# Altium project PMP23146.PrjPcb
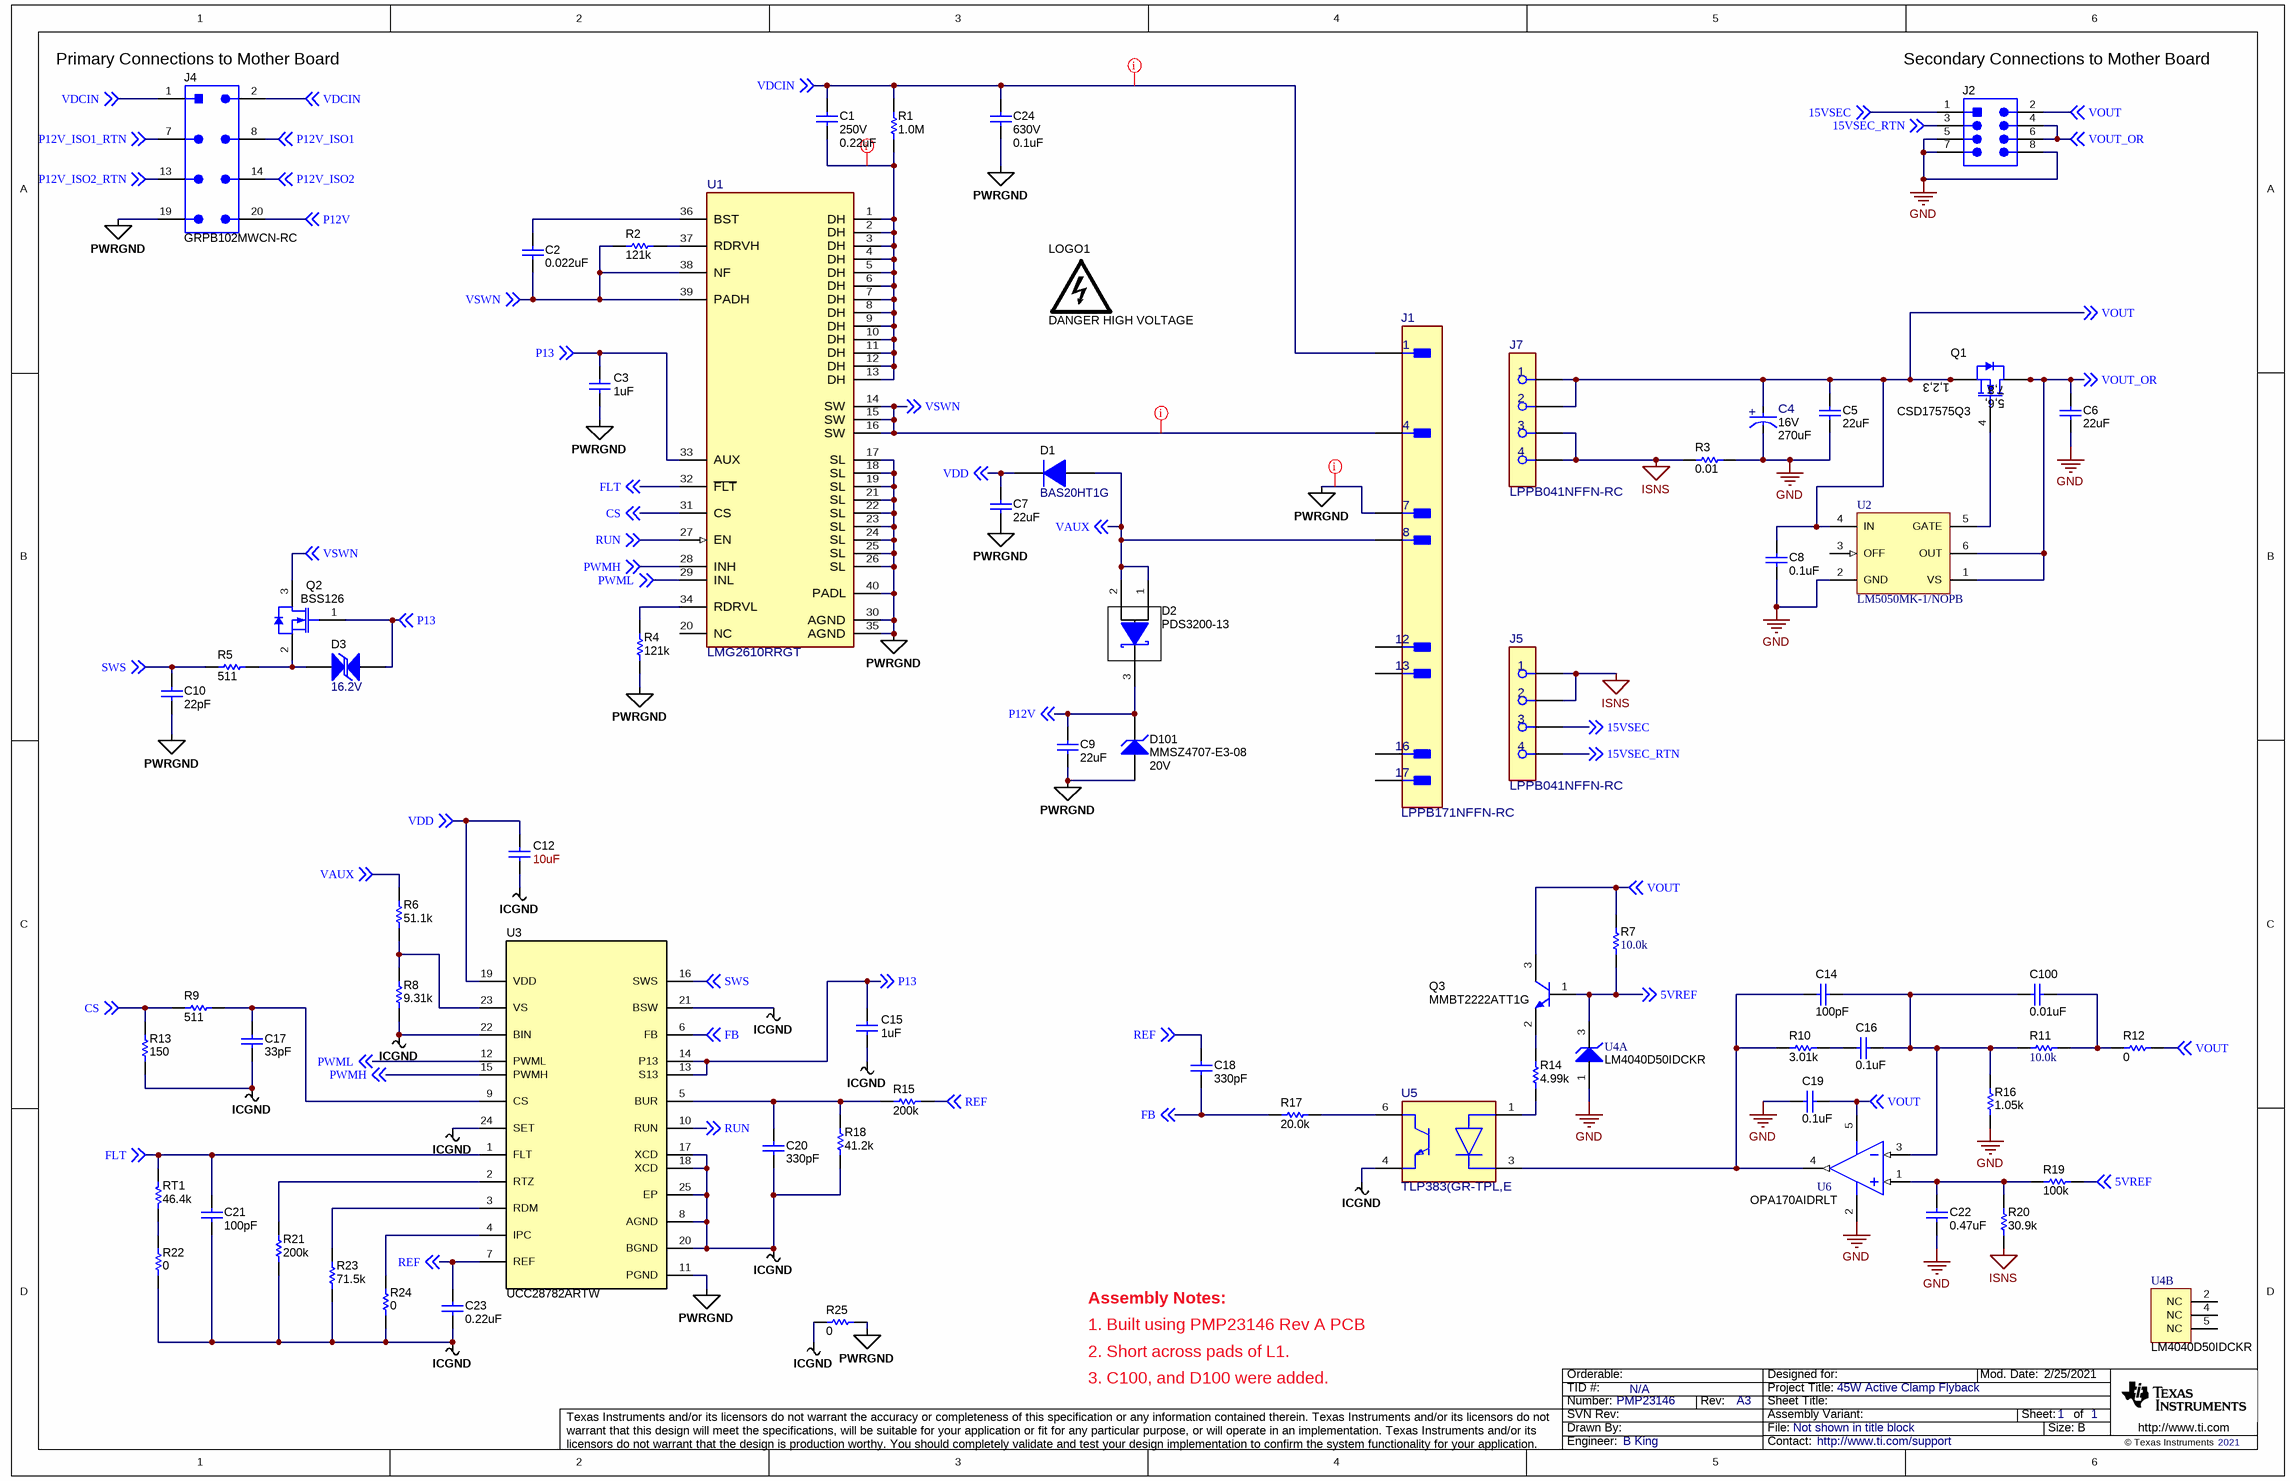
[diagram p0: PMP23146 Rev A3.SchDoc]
TID: N/A; TechSupport: http://www.ti.com/support; SCH_Rev: A3; PRJ_Title: 45W Active Clamp Flyback; PRJ_Number: PMP23146; PRJ_Engineer: B King; PCB_Rev: A; PCB_Layout: B King; CopyrightYear: 2021
1 sheet, 68 parts. Net scope: global (net labels, ports and power ports of the same name join across sheets).
Board file: PMP23146 Rev A.PcbDoc

## Sheet PMP23146 Rev A3.SchDoc
size 431 x 279 mm; Date: Not shown in title block; ApprovedBy: Not shown in title block; CheckedBy: Not shown in title block; Author: Not shown in title block; CompanyName: Not shown in title block; Engineer: Not shown in title block; Organization: Not shown in title block; Address1: Not shown in title block; Address2: Not shown in title block; Address3: Not shown in title block; Address4: Not shown in title block; DocumentNumber: 1; Revision: Use project parameter SCH_Rev; SheetNumber: 1; SheetTotal: 1; PageSetup: Record=PageOptions¦CenterHorizontal=True¦CenterVertical=True¦PrintScale=1.00¦XCorrection=1.00¦YCorrection=1.00¦PrintKind=0¦BorderSize=5000000¦LeftOffset=0¦BottomOffset=0¦Orientation=2¦PaperLength=1000¦PaperWidth=1000¦Scale=100¦PaperSource=15¦PrintQuality=600¦MediaType=1¦DitherType=10¦PaperKind=Letter¦PrintScaleMode=1

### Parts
C1  VDC_V: 250V  ValueDisplayed: 0.22uF  [1206_190L]  (hidden comment: C3216X7T2E224K160AA)
C2  ValueDisplayed: 0.022uF  [0402S]  (hidden comment: GRM155R71H223KA12D)
C3  ValueDisplayed: 1uF  [0603S]  (hidden comment: C1608X7R1E105K080AB)
C4  VDC_V: 16V  ValueDisplayed: 270uF  [FP-APSG160ELL271MF08J_RADIAL-MFG]  (hidden comment: APSG160ELL271MF08J)
C5  ValueDisplayed: 22uF  [1206_180L]  (hidden comment: C3216X5R1V226M160AC)
C6  ValueDisplayed: 22uF  [1206_180L]  (hidden comment: C3216X5R1V226M160AC)
C7  ValueDisplayed: 22uF  [1206_180L]  (hidden comment: C3216X5R1V226M160AC)
C8  ValueDisplayed: 0.1uF  [0402S]  (hidden comment: GRM155R71E104KE14D)
C9  ValueDisplayed: 22uF  [1206_180L]  (hidden comment: C3216X5R1V226M160AC)
C10  ValueDisplayed: 22pF  [0402S]  (hidden comment: GRM1555C1H220JA01D)
C12  ValueDisplayed: 10uF  [0603S]  (hidden comment: GRM188R6YA106MA73D)
C14  ValueDisplayed: 100pF  [0402S]  (hidden comment: GRM1555C1H101JA01D)
C15  ValueDisplayed: 1uF  [0603S]  (hidden comment: C1608X7R1E105K080AB)
C16  ValueDisplayed: 0.1uF  [0402S]  (hidden comment: GRM155R71E104KE14D)
C17  ValueDisplayed: 33pF  [0402S]  (hidden comment: GRM1555C1H330JA01D)
C18  ValueDisplayed: 330pF  [0402S]  (hidden comment: GRM155R71H331KA01D)
C19  ValueDisplayed: 0.1uF  [0402S]  (hidden comment: GRM155R71E104KE14D)
C20  ValueDisplayed: 330pF  [0402S]  (hidden comment: GRM155R71H331KA01D)
C21  ValueDisplayed: 100pF  [0402S]  (hidden comment: GRM1555C1H101JA01D)
C22  ValueDisplayed: 0.47uF  [0402]  (hidden comment: C1005X5R1A474K050BB)
C23  ValueDisplayed: 0.22uF  [0402S]  (hidden comment: GRM155R71C224KA12D)
C24  VDC_V: 630V  ValueDisplayed: 0.1uF  [1808_215_L]  (hidden comment: C1808W104KBRACTU)
C100  ValueDisplayed: 0.01uF  [0402S]  (hidden comment: GCM155R71E103KA37D)
D1  BAS20HT1G  [SOD-323]
D2  PDS3200-13  [POWERDI5]
D3  value 16.2V  [SOD-323-Bi]  (hidden comment: DF2B18FU)
D101  MMSZ4707-E3-08  value 20V  [SOD-123]
J1  LPPB171NFFN-RC  [FP-GRPB171VWVN-RC_HDR17-MFG]
J2  GRPB042MWCN-RC  [Sullins_GRPB042MWCN]  (value not drawn)
J4  GRPB102MWCN-RC  [Sullins_GRPB102MWCN-modified]
J5  LPPB041NFFN-RC  [FP-LPPB041NFFN-RC_HDR04-MFG]
J7  LPPB041NFFN-RC  [FP-LPPB041NFFN-RC_HDR04-MFG]
LOGO1  DANGER HIGH VOLTAGE  [IEC_HighVoltage_Small]  (no BOM)
Q1  CSD17575Q3  [DQG0008A_NV]
Q2  BSS126  [SOT-23L]
Q3  MMBT2222ATT1G  [SOT-416]
R1  ValueDisplayed: 1.0M  [1206L]  (hidden comment: CRCW12061M00JNEA)
R2  ValueDisplayed: 121k  [0402S]  (hidden comment: CRCW0402121KFKED)
R3  ValueDisplayed: 0.01  [1206L]  (hidden comment: CSR1206FK10L0)
R4  ValueDisplayed: 121k  [0402S]  (hidden comment: CRCW0402121KFKED)
R5  ValueDisplayed: 511  [0402S]  (hidden comment: CRCW0402511RFKED)
R6  ValueDisplayed: 51.1k  [0402S]  (hidden comment: CRCW040251K1FKED)
R7  ValueDisplayed: 10.0k  [0402S]  (hidden comment: CRCW040210K0FKED)
R8  ValueDisplayed: 9.31k  [0402S]  (hidden comment: CRCW04029K31FKED)
R9  ValueDisplayed: 511  [0402S]  (hidden comment: CRCW0402511RFKED)
R10  ValueDisplayed: 3.01k  [0402S]  (hidden comment: CRCW04023K01FKED)
R11  ValueDisplayed: 10.0k  [0402S]  (hidden comment: CRCW040210K0FKED)
R12  ValueDisplayed: 0  [0402S]  (hidden comment: RC0402JR-070RL)
R13  ValueDisplayed: 150  [0402S]  (hidden comment: CRCW0402150RFKED)
R14  ValueDisplayed: 4.99k  [0402S]  (hidden comment: CRCW04024K99FKED)
R15  ValueDisplayed: 200k  [0402S]  (hidden comment: CRCW0402200KFKED)
R16  ValueDisplayed: 1.05k  [0402S]  (hidden comment: CRCW04021K05FKED)
R17  ValueDisplayed: 20.0k  [0402S]  (hidden comment: CRCW040220K0FKED)
R18  ValueDisplayed: 41.2k  [0402S]  (hidden comment: CRCW040241K2FKED)
R19  ValueDisplayed: 100k  [0402S]  (hidden comment: CRCW0402100KFKED)
R20  ValueDisplayed: 30.9k  [0402S]  (hidden comment: CRCW040230K9FKED)
R21  ValueDisplayed: 200k  [0402S]  (hidden comment: CRCW0402200KFKED)
R22  ValueDisplayed: 0  [0402S]  (hidden comment: CRCW04020000Z0ED)
R23  ValueDisplayed: 71.5k  [0402S]  (hidden comment: CRCW040271K5FKED)
R24  ValueDisplayed: 0  [0402S]  (hidden comment: CRCW04020000Z0ED)
R25  ValueDisplayed: 0  [0402S]  (hidden comment: CRCW04020000Z0ED)
RT1  ValueDisplayed: 46.4k  [0603L]  (hidden comment: CRCW060346K4FKEA)
U1  LMG2610RRGT  [RRG0038A-MFG]
U2  LM5050MK-1/NOPB  [DDC0006A_L]
U3  UCC28782ARTW  [RTW0024B]
U4  LM4040D50IDCKR  [DCK0005A_L]  (parts A,B of 2)
U5  TLP383(GR-TPL,E  [FP-TLP383(GR-TPL,E_SO6-4-MFG]
U6  OPA170AIDRLT  [DRL0005A]

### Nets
GND: C4.1(CATHODE) C5.1 C6.2 C8.2 C19.1 C22.1 J2.5 J2.7 J2.8 R3.2 R16.1 U2.2(GND) U4.1(ANODE) U6.2(V-)
ICGND: C12.2 C15.1 C17.2 C20.1 C21.2 C23.2 R8.1 R13.1 R18.1 R21.1 R22.1 R23.1 R24.1 R25.2 U3.8(AGND) U3.17(XCD) U3.18(XCD) U3.20(BGND) U3.21(BSW) U3.22(BIN) U3.24(SET) U3.25(EP) U5.4(Emitter)
ISNS: J5.1 J5.2 J7.3 J7.4 R3.1 R20.1
PWRGND: C3.1 C7.2 C9.2 C10.1 C24.2 D101.2(A) J1.7 J4.19 R4.1 R25.1 U1.17(SL) U1.18(SL) U1.19(SL) U1.21(SL) U1.22(SL) U1.23(SL) U1.24(SL) U1.25(SL) U1.26(SL) U1.30(AGND) U1.35(AGND) U1.40(PADL) U3.11(PGND)
5VREF: Q3.1(B) R7.1 R19.2 U4.3(CATHODE) ; off-sheet 5VREF
15VSEC: J2.1 J5.3 ; off-sheet 15VSEC
15VSEC_RTN: J2.3 J5.4 ; off-sheet 15VSEC_RTN
CS: R9.1 R13.2 U1.31(CS) ; off-sheet CS
FB: C18.1 R17.1 U3.6(FB) ; off-sheet FB
FLT: C21.1 RT1.1 U1.32(~{FLT}) U3.1(FLT) ; off-sheet FLT
P12V: C9.1 D2.3(K) D101.1(K) J4.20 ; off-sheet P12V
P12V_ISO1: J4.8 ; off-sheet P12V_ISO1
P12V_ISO1_RTN: J4.7 ; off-sheet P12V_ISO1_RTN
P12V_ISO2: J4.14 ; off-sheet P12V_ISO2
P12V_ISO2_RTN: J4.13 ; off-sheet P12V_ISO2_RTN
P13: C3.2 C15.2 D3.2 Q2.1(G) U1.33(AUX) U3.13(S13) U3.14(P13) ; off-sheet P13
PWMH: U1.28(INH) U3.15(PWMH) ; off-sheet PWMH
PWML: U1.29(INL) U3.12(PWML) ; off-sheet PWML
REF: C18.2 C23.1 R15.2 U3.7(REF) ; off-sheet REF
RUN: U1.27(EN) U3.10(RUN) ; off-sheet RUN
SWS: C10.2 R5.1 U3.16(SWS) ; off-sheet SWS
VAUX: D1.2(A) D2.1(A) D2.2(A) J1.8 R6.2 ; off-sheet VAUX
VDCIN: C1.1 C24.1 J1.1 J4.1 J4.2 R1.2 ; off-sheet VDCIN
VDD: C7.1 C12.1 D1.1(K) U3.19(VDD) ; off-sheet VDD
VOUT: C4.2(ANODE) C5.2 C8.1 C19.2 J2.2 J7.1 J7.2 Q1.1(S) Q1.2(S) Q1.3(S) Q3.3(C) R7.2 R12.1 U2.4(IN) U6.5(V+) ; off-sheet VOUT
VOUT_OR: C6.1 J2.4 J2.6 Q1.5(D) Q1.6(D) Q1.7(D) Q1.8(D) Q1.9(D) U2.1(VS) U2.6(OUT) ; off-sheet VOUT_OR
VSWN: C2.2 J1.4 Q2.3(D) R2.1 U1.14(SW) U1.15(SW) U1.16(SW) U1.38(NF) U1.39(PADH) ; off-sheet VSWN
NetC1_2: C1.2 R1.1 U1.1(DH) U1.2(DH) U1.3(DH) U1.4(DH) U1.5(DH) U1.6(DH) U1.7(DH) U1.8(DH) U1.9(DH) U1.10(DH) U1.11(DH) U1.12(DH) U1.13(DH)
NetC2_1: C2.1 U1.36(BST)
NetC14_1: C14.1 R10.1 U5.3(Cathode) U6.4(OUT)
NetC14_2: C14.2 C16.1 C100.1 R11.2 R16.2 U6.3(IN-)
NetC16_2: C16.2 R10.2
NetC17_1: C17.1 R9.2 U3.9(CS)
NetC20_2: C20.2 R15.1 R18.2 U3.5(BUR)
NetC22_2: C22.2 R19.1 R20.2 U6.1(IN+)
NetC100_2: C100.2 R11.1 R12.2
NetD3_1: D3.1 Q2.2(S) R5.2
NetQ1_4: Q1.4(G) U2.5(GATE)
NetQ3_2: Q3.2(E) R14.2
NetR2_2: R2.2 U1.37(RDRVH)
NetR4_2: R4.2 U1.34(RDRVL)
NetR6_1: R6.1 R8.2 U3.23(VS)
NetR14_1: R14.1 U5.1(Anode)
NetR17_2: R17.2 U5.6(Collector)
NetR21_2: R21.2 U3.2(RTZ)
NetR22_2: R22.2 RT1.2
NetR23_2: R23.2 U3.3(RDM)
NetR24_2: R24.2 U3.4(IPC)

Not connected (* = marked no-connect by the designer): J1 12 13 16 17; U1 20(NC); U2 3(OFF); U4 2(NC) 4(NC) 5(NC)

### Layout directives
net class 400V: NetC1_2, VDCIN, VSWN
net class Primary LV: PWRGND

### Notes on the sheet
- (near J4) Primary Connections to Mother Board
- (near J2) Secondary Connections to Mother Board
- 1. Built using PMP23146 Rev A PCB
- Assembly Notes:
- 2. Short across pads of L1.
- 3. C100, and D100 were added.

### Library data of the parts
C1 = CMP-0008726-2: CAP, CERM, 0.22 uF, 250 V, +/- 10%, X7T, 1206_190; Manufacturer: TDK; TaMin_C: -55°C; Polarized: N; SizeAreaWB_mm2: 10.92; Value1: Unknown; U/M: EA; Value: 0.22uF; TaMax_C: 125°C; SizeZ_mm: 1.9; SizeX_mm: 3.2; SizeY_mm: 1.6; Cap_Case: 1206; SizeArea_mm2: 5.12; Cap_F: 220nF; AEC Category: Q200
C2 = CMP-0006684-2: CAP, CERM, 0.022 uF, 50 V, +/- 10%, X7R, 0402; Manufacturer: MuRata; TaMin_C: -55°C; Polarized: N; SizeAreaWB_mm2: 3; Value1: Unknown; U/M: EA; TaMax_C: 125°C; SizeZ_mm: 0.6; SizeX_mm: 1; SizeY_mm: 0.5; Cap_Case: 0402; Value2: 50V; Cap_F: 22nF; AEC Category: Q200
C3 C15 = CMP-0007040-4: CAP, CERM, 1 µF, 25 V, +/- 10%, X7R, 0603; Manufacturer: TDK; Polarized: N; CompType: Capacitor; Value: 1uF; U/M: EA; Cap_F: 1µF; Value1: Unknown; VDC_V: 25V; TaMin_C: -55°C; TaMax_C: 125°C; Cap_Case: 0603; AEC Category: Q200; SizeArea_mm2: 1.28; SizeAreaWB_mm2: 4.68; SizeX_mm: 1.6; SizeY_mm: 0.8; SizeZ_mm: 1
C4 = CMP-0091874-1: 270µF 16V Aluminum - Polymer Capacitors Radial, Can 10mOhm 20000 Hrs @ 105°C; Manufacturer: Nippon Chemi-Con; IRMS_A: 5.08A; AEC Qualified: No; Esr: 0.01; Tolerance_%: 20%; SizeZ_mm: 9.2mm; Dissipation Factor: 12%; Life: 20000Hours; Leakage Current: 864uA
C5-C7 C9 = CMP-0008667-2: CAP, CERM, 22 uF, 35 V, +/- 20%, X5R, 1206; Manufacturer: TDK; TaMin_C: -55°C; ESR_ohm: 2.398m; Polarized: N; SizeAreaWB_mm2: 10.92; Value1: 0.002398 ohm; U/M: EA; Value: 22uF; TaMax_C: 85°C; SizeZ_mm: 1.8; SizeX_mm: 3.2; SizeY_mm: 1.6; Cap_Case: 1206_180; Value2: 35V; SizeArea_mm2: 5.12; Cap_F: 22µF; IRMS_A: 4.68507A; AEC Category: Q200
C8 C16 C19 = CMP-0006659-2: CAP, CERM, 0.1 uF, 25 V, +/- 10%, X7R, 0402; Manufacturer: MuRata; TaMin_C: -55°C; Polarized: N; SizeAreaWB_mm2: 3; Value1: Unknown; U/M: EA; Value: 0.1uF; TaMax_C: 125°C; SizeZ_mm: 0.6; SizeX_mm: 1; SizeY_mm: 0.5; Cap_Case: 0402; Value2: 25V; Cap_F: 100nF; AEC Category: Q200
C10 = CMP-0006439-2: CAP, CERM, 22 pF, 50 V, +/- 5%, C0G/NP0, 0402; Manufacturer: MuRata; TaMin_C: -55°C; Polarized: N; SizeAreaWB_mm2: 3; Value1: Unknown; U/M: EA; Value: 22pF; TaMax_C: 125°C; SizeZ_mm: 0.6; SizeX_mm: 1; SizeY_mm: 0.5; Cap_Case: 0402; Value2: 50V; AEC Category: Q200
C12 = CMP-0007009-5: CAP, CERM, 10 µF, 35 V, +/- 10%, X5R, 0603; Manufacturer: Murata; TaMin_C: -55°C; ESR_ohm: 4.211m; Polarized: N; SizeAreaWB_mm2: 4.68; Value1: 0.004211 ohm; U/M: EA; Value: 10uF; TaMax_C: 85°C; SizeZ_mm: 1; SizeX_mm: 1.6; SizeY_mm: 0.8; Cap_Case: 0603; Value2: 35V; SizeArea_mm2: 1.28; Cap_F: 10µF; IRMS_A: 2.534067A
C14 C21 = CMP-0006410-2: CAP, CERM, 100 pF, 50 V, +/- 5%, C0G/NP0, 0402; Manufacturer: MuRata; TaMin_C: -55°C; Polarized: N; SizeAreaWB_mm2: 3; Value1: Unknown; U/M: EA; Value: 100pF; TaMax_C: 125°C; SizeZ_mm: 0.6; SizeX_mm: 1; SizeY_mm: 0.5; Cap_Case: 0402; Value2: 50V; AEC Category: Q200
C17 = CMP-0006454-2: CAP, CERM, 33 pF, 50 V, +/- 5%, C0G/NP0, 0402; Manufacturer: MuRata; TaMin_C: -55°C; Polarized: N; SizeAreaWB_mm2: 3; Value1: Unknown; U/M: EA; Value: 33pF; TaMax_C: 125°C; SizeZ_mm: 0.6; SizeX_mm: 1; SizeY_mm: 0.5; Cap_Case: 0402; Value2: 50V; AEC Category: Q200
C18 C20 = CMP-0006687-2: CAP, CERM, 330 pF, 50 V, +/- 10%, X7R, 0402; Manufacturer: MuRata; TaMin_C: -55°C; Polarized: N; SizeAreaWB_mm2: 3; Value1: Unknown; U/M: EA; Value: 330pF; TaMax_C: 125°C; SizeZ_mm: 0.6; SizeX_mm: 1; SizeY_mm: 0.5; Cap_Case: 0402; Value2: 50V; AEC Category: Q200
C22 = CMP-0006267-3: CAP, CERM, 0.47 uF, 10 V, +/- 10%, X5R, 0402; Manufacturer: TDK; AEC Category: Q200; SizeZ_mm: 0.6; SizeY_mm: 0.5; SizeX_mm: 1; Value2: 10V; MFG_Status: TI_Obsolete; SizeAreaWB_mm2: 3; Cap_F: 470nF; TaMin_C: -55°C; TaMax_C: 85°C; U/M: EA; Value: 0.47uF; Value1: Unknown; Polarized: N
C23 = CMP-0006648-2: CAP, CERM, 0.22 µF, 16 V, +/- 10%, X7R, 0402; Manufacturer: MuRata; TaMin_C: -55°C; Polarized: N; SizeAreaWB_mm2: 3; Value1: Unknown; U/M: EA; Value: 0.22uF; TaMax_C: 125°C; SizeZ_mm: 0.6; SizeX_mm: 1; SizeY_mm: 0.5; Cap_Case: 0402; Value2: 16V; Cap_F: 220nF; AEC Category: Q200
C24 = CMP-0009318-2: CAP, CERM, 0.1 uF, 630 V, +/- 10%, X7R, 1808; Manufacturer: Kemet; TaMin_C: -55°C; Polarized: N; SizeAreaWB_mm2: 16.5; Value1: Unknown; U/M: EA; Value: 0.1uF; TaMax_C: 125°C; SizeZ_mm: 2.15; SizeX_mm: 4.5; SizeY_mm: 2; Cap_Case: 1808; SizeArea_mm2: 9; Cap_F: 100nF; AEC Category: Q200
C100 = CMP-0006352-2: CAP, CERM, 0.01 uF, 25 V, +/- 10%, X7R, 0402; Manufacturer: MuRata; TaMin_C: -55°C; Polarized: N; SizeAreaWB_mm2: 3; Value1: Unknown; U/M: EA; Value: 0.01uF; TaMax_C: 125°C; SizeZ_mm: 0.6; SizeX_mm: 1; SizeY_mm: 0.5; Cap_Case: 0402; Value2: 25V; Cap_F: 10nF; AEC Category: Q200
D1 = CMP-0029150-2: Diode, Switching, 200 V, 0.2 A, AEC-Q101, SOD-323; Manufacturer: ON Semiconductor; Value2: 1.25V; Value1: 0.2A; SizeZ_mm: 1; Green_REACh: Incomplete; SizeArea_mm2: 3.645; Vr_V: 200V; SizeX_mm: 2.7; TJmax_C: 150°C; Io_A: 200mA; Value: 200V; Green_Lifecycle: Not Set; SizeAreaWB_mm2: 8.695; AEC Qualified: Y; AEC Category: Q101; SizeY_mm: 1.35
D2 = CMP-0077025-2: Diode, Schottky, 200 V, 3 A, PowerDI5; Manufacturer: Diodes Inc.; Green_REACh: Incomplete; Value2: 0.78V; TJmax_C: 150°C; Green_Lifecycle: Not Set; Io_A: 3A; SizeX_mm: 6.4; SizeAreaWB_mm2: 49.56; Vf_V: 780mV; SizeY_mm: 3.9; AEC Category: Q101; SizeArea_mm2: 24.96; Value: 200V; SizeZ_mm: 1.05
D3 = CMP-0005821-3: Diode, TVS, Bi, 16.2 V, SOD-323; Manufacturer: Toshiba; PartNumber: DF2B18FU,H3F; SizeAreaWB_mm2: 8.695; Ppk: 80W; SizeZ_mm: 1; SizeY_mm: 1.35; SizeArea_mm2: 3.645; VRWM: 15V; SizeX_mm: 2.7
D101 = CMP-0077617-3: Diode, Zener, 20 V, 500 mW, SOD-123; Manufacturer: Vishay-Semiconductor; Power_W: 500mW; AEC Category: Q101; SizeX_mm: 3.85; AEC Qualified: N; SizeZ_mm: 1.35; RJA_CperW: 340; Value1: 0.5W; SizeAreaWB_mm2: 13.095; SizeArea_mm2: 6.545; SizeY_mm: 1.7
J1 = CMP-BK1: Connector Socket Through Hole 17 position 0.050" (1.27mm); Manufacturer: Sullins Connector Solutions; Part Number: GRPB171VWVN-RC; Conn Gender: Male; SizeZ_mm: 4.4mm; ContactFinish: Gold; Current_A: 1A; Row_Count: 1; Conn Orientation: Straight; AEC Qualified: No
J2 = CMP-0086278-1: Header, 1.27mm, 4x2, Gold, R/A, TH; Manufacturer: Sullins Connector Solutions; Current_A: 1A; Shrouded: N; Pitch_mm: 1.27; Voltage_V: 500V; Gender: Male; Row_Count: 2
J4 = CMP-0054702-2: Header, 50mil, 10x2, Gold, R/A, TH; Manufacturer: Sullins Connector Solutions
J5 J7 = CMP-0092135-1: Manufacturer: Sullins Connector Solutions; Row_Count: 1; AEC Qualified: No; Conn Gender: Female; Current_A: 1A; Is Female: yes; ContactFinish: Gold,Nickel; SizeZ_mm: 4.7mm; DUT-Pitch_mm: 1.27mm; Conn Orientation: Straight
LOGO1 = CMP-0074835-1: IEC 61010-1 High Voltage Warning; SymbolCreator: a0412235
Q1 = CMP-0000587-1: MOSFET, N-CH, 30 V, 60 A, DQG0008A (VSON-CLIP-8); Alternate Manufacturer: None; Manufacturer: Texas Instruments; SizeZ_mm: 1.1; ChType: N; Value2: 23 nC; Value1: 0.003; VdsMax_V: 30V; SizeX_mm: 3.3; Vgs_V: 20V; Value: 30V; Rdson45_ohm: 3.2m; SizeArea_mm2: 10.89; AEC Category: Q101; IdsMax_A: 60A; SizeAreaWB_mm2: 18.49; U/M: EA; QgTyp_nC: 23
Q2 = CMP-0067574-1: MOSFET, N-CH, 600 V, 0.021 A, AEC-Q101, SOT-23; PartNumber: BSS126H6327XTSA2; Manufacturer: Infineon Technologies; Alternate Manufacturer: None; U/M: EA; ChType: N; Value: 600V; Value1: ? ohm; Value2: 1.4 nC; QgTyp_nC: 1.4; Vgs_V: 20V; IdsMax_A: 21mA; SizeAreaWB_mm2: 14.0; SizeArea_mm2: 7.5; SizeX_mm: 2.5; SizeY_mm: 3.0; SizeZ_mm: 1.1; AEC Category: Q101; AEC Qualified: Y
Q3 = CMP-0078773-2: Transistor, NPN, 40 V, 0.6 A, AEC-Q101, SOT-416; Manufacturer: ON Semiconductor; Value: 40 V; Value1: 0.6 A; NPN: 1; PNP: 0; Vceo_V: 40V; AEC Category: Q101; SizeZ_mm: 0.95; AEC Qualified: Y; TaMin_C: -55°C; SizeArea_mm2: 2.56; Vcesat1_V: 300mV; IcRated_A: 600mA; TaMax_C: 150°C; CompType: BJT; SizeX_mm: 1.6; SizeAreaWB_mm2: 6.76
R1 = CMP-0018610-3: RES, 1.0 M, 5%, 0.25 W, AEC-Q200 Grade 0, 1206; Manufacturer: Vishay-Dale; Power_W: 250mW; TempCo: 200 ppm/C; Value_Code: 1M00; Value: 1.0Meg; EIA_Code: E24; Res_ohm: 1M; SizeX_mm: 3.2; SizeY_mm: 1.6; SizeZ_mm: 1.35; Value2: 0.25W; SizeArea_mm2: 5.12; AEC Qualified: Y; VDC_V: 200V; AEC Category: Q200; AEC Grade: 0
R2 R4 = CMP-0025984-3: RES, 121 k, 1%, 0.063 W, AEC-Q200 Grade 0, 0402; Manufacturer: Vishay-Dale; Power_W: 63mW; TempCo: 100 ppm/C; Value: 121k; EIA_Code: E96; SizeX_mm: 1; SizeY_mm: 0.5; SizeZ_mm: 0.6; Value2: 0.063W; AEC Qualified: Y; VDC_V: 50V; AEC Category: Q200; AEC Grade: 0
R3 = CMP-0017256-2: RES, 0.01, 1%, 0.5 W, 1206; Manufacturer: Stackpole Electronics Inc; Power_W: 500mW; TempCo: 100 ppm/C; Value_Code: R010; U/M: EA; Value: 0.01; EIA_Code: E96; Res_ohm: 10m; SizeX_mm: 3.2; SizeY_mm: 1.6; SizeZ_mm: 1.35; Value2: 0.5W; SizeArea_mm2: 5.12; AEC Category: Q200
R5 R9 = CMP-0026436-2: RES, 511, 1%, 0.063 W, AEC-Q200 Grade 0, 0402; Manufacturer: Vishay-Dale; Power_W: 63mW; TempCo: 100 ppm/C; Value_Code: 511R; Value: 511; EIA_Code: E96; SizeX_mm: 1; SizeY_mm: 0.5; SizeZ_mm: 0.6; Value2: 0.063W; AEC Qualified: Y; VDC_V: 50V; AEC Category: Q200; AEC Grade: 0
R6 = CMP-0026437-2: RES, 51.1 k, 1%, 0.063 W, AEC-Q200 Grade 0, 0402; Manufacturer: Vishay-Dale; Power_W: 63mW; TempCo: 100 ppm/C; Value_Code: 51k1; Value: 51.1k; EIA_Code: E96; SizeX_mm: 1; SizeY_mm: 0.5; SizeZ_mm: 0.6; Value2: 0.063W; AEC Qualified: Y; VDC_V: 50V; AEC Category: Q200; AEC Grade: 0
R7 R11 = CMP-0025958-1: RES, 10.0 k, 1%, 0.063 W, 0402; Manufacturer: Vishay-Dale; Power_W: 63mW; TempCo: 100 ppm/C; Value_Code: 10k0; U/M: EA; Value: 10.0k; EIA_Code: E96; Res_ohm: 10k; SizeX_mm: 1; SizeY_mm: 0.5; SizeZ_mm: 0.6; Value2: 0.063W; VDC_V: 50V; AEC Category: Q200
R8 = CMP-0026620-3: RES, 9.31 k, 1%, 0.063 W, AEC-Q200 Grade 0, 0402; Manufacturer: Vishay-Dale; Power_W: 63mW; TempCo: 100 ppm/C; Value_Code: 9k31; Value: 9.31k; EIA_Code: E96; SizeX_mm: 1; SizeY_mm: 0.5; SizeZ_mm: 0.6; Value2: 0.063W; AEC Qualified: Y; VDC_V: 50V; AEC Category: Q200; AEC Grade: 0
R10 = CMP-0026329-2: RES, 3.01 k, 1%, 0.063 W, AEC-Q200 Grade 0, 0402; Manufacturer: Vishay-Dale; Power_W: 63mW; TempCo: 100 ppm/C; Value_Code: 3k01; Value: 3.01k; EIA_Code: E96; SizeX_mm: 1; SizeY_mm: 0.5; SizeZ_mm: 0.6; Value2: 0.063W; AEC Qualified: Y; VDC_V: 50V; AEC Category: Q200; AEC Grade: 0
R12 = CMP-0027004-2: RES, 0, 5%, 0.063 W, 0402; Manufacturer: Yageo America; Power_W: 63mW; TempCo: 200 ppm/C; Value_Code: 0000; U/M: EA; Value: 0; EIA_Code: E24; SizeX_mm: 1; SizeY_mm: 0.5; SizeZ_mm: 0.6; Value2: 0.063W; CompType: Resistor; VDC_V: 50V; AEC Category: Q200
R13 = CMP-0026022-3: RES, 150, 1%, 0.063 W, AEC-Q200 Grade 0, 0402; Manufacturer: Vishay-Dale; Power_W: 63mW; TempCo: 100 ppm/C; Value_Code: 150R; Value: 150; EIA_Code: E96; SizeX_mm: 1; SizeY_mm: 0.5; SizeZ_mm: 0.6; Value2: 0.063W; AEC Qualified: Y; VDC_V: 50V; AEC Category: Q200; AEC Grade: 0
R14 = CMP-0026414-2: RES, 4.99 k, 1%, 0.063 W, AEC-Q200 Grade 0, 0402; Manufacturer: Vishay-Dale; Power_W: 63mW; TempCo: 100 ppm/C; Value_Code: 4k99; Value: 4.99k; EIA_Code: E96; SizeX_mm: 1; SizeY_mm: 0.5; SizeZ_mm: 0.6; Value2: 0.063W; AEC Qualified: Y; VDC_V: 50V; AEC Category: Q200; AEC Grade: 0
R15 R21 = CMP-0026158-2: RES, 200 k, 1%, 0.063 W, AEC-Q200 Grade 0, 0402; Manufacturer: Vishay-Dale; Power_W: 63mW; TempCo: 100 ppm/C; Value: 200k; EIA_Code: E96; SizeX_mm: 1; SizeY_mm: 0.5; SizeZ_mm: 0.6; Value2: 0.063W; AEC Qualified: Y; VDC_V: 50V; AEC Category: Q200; AEC Grade: 0
R16 = CMP-0026073-3: RES, 1.05 k, 1%, 0.063 W, AEC-Q200 Grade 0, 0402; Manufacturer: Vishay-Dale; Power_W: 63mW; TempCo: 100 ppm/C; Value_Code: 1k05; Value: 1.05k; EIA_Code: E96; SizeX_mm: 1; SizeY_mm: 0.5; SizeZ_mm: 0.6; Value2: 0.063W; AEC Qualified: Y; VDC_V: 50V; AEC Category: Q200; AEC Grade: 0
R17 = CMP-0026162-2: RES, 20.0 k, 1%, 0.063 W, AEC-Q200 Grade 0, 0402; Manufacturer: Vishay-Dale; Power_W: 63mW; TempCo: 100 ppm/C; Value_Code: 20k0; Value: 20.0k; EIA_Code: E96; Res_ohm: 20k; SizeX_mm: 1; SizeY_mm: 0.5; SizeZ_mm: 0.6; Value2: 0.063W; AEC Qualified: Y; VDC_V: 50V; AEC Category: Q200; AEC Grade: 0
R18 = CMP-0026371-2: RES, 41.2 k, 1%, 0.063 W, AEC-Q200 Grade 0, 0402; Manufacturer: Vishay-Dale; Power_W: 63mW; TempCo: 100 ppm/C; Value_Code: 41k2; Value: 41.2k; EIA_Code: E96; SizeX_mm: 1; SizeY_mm: 0.5; SizeZ_mm: 0.6; Value2: 0.063W; AEC Qualified: Y; VDC_V: 50V; AEC Category: Q200; AEC Grade: 0
R19 = CMP-0025950-3: RES, 100 k, 1%, 0.063 W, AEC-Q200 Grade 0, 0402; Manufacturer: Vishay-Dale; Power_W: 63mW; TempCo: 100 ppm/C; Value: 100k; EIA_Code: E96; SizeX_mm: 1; SizeY_mm: 0.5; SizeZ_mm: 0.6; Value2: 0.063W; AEC Qualified: Y; VDC_V: 50V; AEC Category: Q200; AEC Grade: 0
R20 = CMP-0026285-2: RES, 30.9 k, 1%, 0.063 W, AEC-Q200 Grade 0, 0402; Manufacturer: Vishay-Dale; Power_W: 63mW; TempCo: 100 ppm/C; Value_Code: 30k9; Value: 30.9k; EIA_Code: E96; SizeX_mm: 1; SizeY_mm: 0.5; SizeZ_mm: 0.6; Value2: 0.063W; AEC Qualified: Y; VDC_V: 50V; AEC Category: Q200; AEC Grade: 0
R22 R24 R25 = CMP-0026822-3: RES, 0, 5%, 0.063 W, AEC-Q200 Grade 0, 0402; Manufacturer: Vishay-Dale; Power_W: 63mW; TempCo: 200 ppm/C; Value_Code: 0000; Value: 0; EIA_Code: E24; SizeX_mm: 1; SizeY_mm: 0.5; SizeZ_mm: 0.6; Value2: 0.063W; CompType: Resistor; AEC Qualified: Y; VDC_V: 50V; AEC Category: Q200
R23 = CMP-0026535-2: RES, 71.5 k, 1%, 0.063 W, AEC-Q200 Grade 0, 0402; Manufacturer: Vishay-Dale; Power_W: 63mW; TempCo: 100 ppm/C; Value_Code: 71k5; Value: 71.5k; EIA_Code: E96; SizeX_mm: 1; SizeY_mm: 0.5; SizeZ_mm: 0.6; Value2: 0.063W; AEC Qualified: Y; VDC_V: 50V; AEC Category: Q200; AEC Grade: 0
RT1 = CMP-0022434-4: RES, 46.4 k, 1%, 0.1 W, AEC-Q200 Grade 0, 0603; Manufacturer: Vishay-Dale; Power_W: 100mW; TempCo: 100 ppm/C; Value_Code: 46k4; Value: 46.4k; EIA_Code: E96; SizeX_mm: 1.6; SizeY_mm: 0.8; SizeZ_mm: 1; Value2: 0.1W; SizeArea_mm2: 1.28; AEC Qualified: Y; VDC_V: 75V; AEC Category: Q200; AEC Grade: 0
U1 = CMP-0092811-1: Integrated 650-V GaN Half-Bridge for Active Clamp Flyback Converters; Manufacturer: Texas Instruments; Turn Off Delay Time: 5ns; Number Of Drivers: 2; Propagation Delay: 50ns; Standoff Height: 0mm; SizeZ_mm: 1mm; Min Supply Voltage: 10V; Output Voltage: 650V; Max Supply Voltage: 26V; TJmax_C: +125°C; AEC Qualified: No
U2 = CMP-0063-01524-2: High Side OR-ing FET Controller, 6-pin TSOT, 1000 Reel; Manufacturer: Texas Instruments; CompType: MiscPower; PowerWise: Y; PackageTopMarking: SZHB*XTT
U3 = CMP-0086087-1: UCC28782ARTW, RTW0024B (WQFN-24); Manufacturer: Texas Instruments; SizeY_mm: 4; SizeZ_mm: 0.8; AEC Category: Q200; SizeArea_mm2: 16; CompType: IC; AEC Qualified: N; SizeAreaWB_mm2: 25
U4 = CMP-0032746-2: Precision Micropower Shunt Voltage Reference, 1% accuracy, 5 V, 15 ppm / degC, 15 mA, -40 to 85 degC, 5-pin SC70 (DCK), Green (RoHS & no Sb/Br); Manufacturer: Texas Instruments; Min Iz for Regulation(uA): 79; Rating: Catalog; Initial Accuracy @ 25/deg C(%): 1; Iout/Iz(Max)(mA): 15; Temp Coeff(Max)(ppm/ degree C): 150; VO(V): 5; AEC Category: Q200; AEC Qualified: N; CompType: IC; SizeAreaWB_mm2: 9.3; SizeArea_mm2: 4.2; SizeX_mm: 2.1; SizeY_mm: 2.0; SizeZ_mm: 1.1
U5 = CMP-0087394-2: Optoisolator Transistor Output 5000Vrms 1 Channel 6-SO; Manufacturer: Toshiba; CTR (Max): 300%; CTR (Min): 100%; SizeZ_mm: 2.3mm
U6 = CMP-0040524-2: MicroPower, Rail-to-Rail Output, General Purpose Operational Amplifier, 2.7 to 36 V, -40 to 125 degC, 5-pin SOT23 (DRL5), Green (RoHS & no Sb/Br); Manufacturer: Texas Instruments; Sub Family: High Supply Voltage Amplifier (>=30V), Low Power Amp (<=500uA), Low Supply Voltage Amplifier (<=2.7V), Precision Amplifier; Total Supply Voltage(Min)(+5V is 5, +/-5V is 10): 2.7; Slew Rate(Typ)(V/us): 0.4; GBW(Typ)(MHz): 1.2; Total Supply Voltage(Max)(+5V is 5, +/-5V is 10): 36; IIB(Max)(pA): 15; Vio (25C)(Max)(mV): 1.8; Rating: Catalog; Offset Drift(Typ)(uV/C): 0.3; Iq per channel(Max)(mA): 0.145; Packing: SMALL T&R; CMRR(Min)(dB): 104; Number of Channels: 1

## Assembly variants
001: not fitted L2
